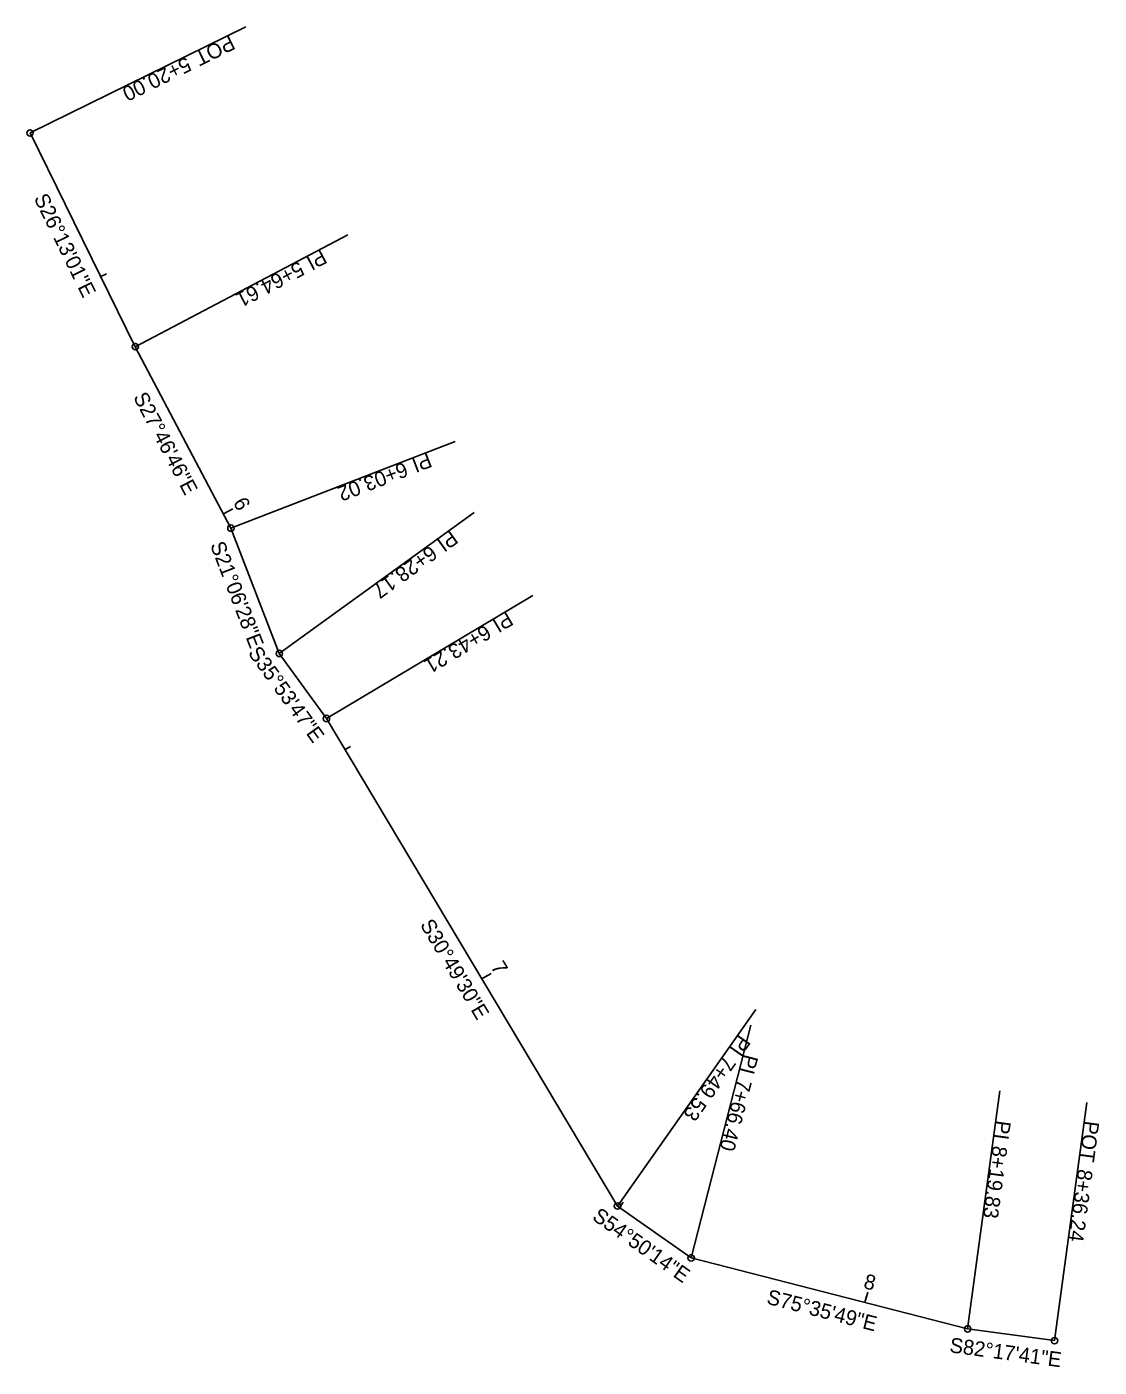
# Model space of a CAD drawing. Extents: x 2352367 to 2352567, y 766880 to 767131.
import ezdxf

# ---------------------------------------------------------------- set-up
doc = ezdxf.new("R2010")
doc.units = 0
for name, color, linetype in [('DR_X_Ditch', 7, 'Continuous'), ('DR_X_Headwall', 7, 'Continuous'), ('GE_P_Alignment', 7, 'Continuous'), ('GE_P_Alignment_100_Stations', 7, 'Continuous'), ('GE_P_Alignment_500_Stations', 7, 'Continuous'), ('RD_X_Fence', 7, 'Continuous'), ('UT_X_Electric', 7, 'Continuous'), ('VG_X_Flower_Bed', 7, 'Continuous'), ('VG_X_Shrub_Line_Lt', 7, 'Continuous')]:
    doc.layers.add(name, color=color, linetype=linetype)

msp = doc.modelspace()

# ---------------------------------------------------------------- linework, layer by layer
at = {"layer": 'DR_X_Ditch'}
for p, q in [((2352367.34, 767110.84), (2352407.71, 767130.72)), ((2352387.05, 767070.82), (2352426.86, 767091.79)), ((2352404.95, 767036.84), (2352446.93, 767053.05)), ((2352414.01, 767013.37), (2352450.46, 767039.75)), ((2352422.83, 767001.19), (2352461.47, 767024.25)), ((2352477.31, 766909.89), (2352503.22, 766946.67)), ((2352491.1, 766900.17), (2352502.29, 766943.76)), ((2352542.85, 766886.88), (2352548.88, 766931.47)), ((2352559.11, 766884.68), (2352565.14, 766929.27))]:
    msp.add_line(p, q, dxfattribs=at)
for centre in [(2352367.34, 767110.84), (2352387.05, 767070.82), (2352404.95, 767036.84), (2352414.01, 767013.37), (2352422.83, 767001.19), (2352477.31, 766909.89), (2352491.1, 766900.17), (2352542.85, 766886.88), (2352559.11, 766884.68)]:
    msp.add_circle(centre, 0.6, dxfattribs=at)
at = {"layer": 'GE_P_Alignment'}
for p, q in [((2352367.34, 767110.84), (2352387.05, 767070.82)), ((2352387.05, 767070.82), (2352404.95, 767036.84)), ((2352404.95, 767036.84), (2352414.01, 767013.37)), ((2352414.01, 767013.37), (2352422.83, 767001.19)), ((2352422.83, 767001.19), (2352477.31, 766909.89)), ((2352477.31, 766909.89), (2352491.1, 766900.17)), ((2352491.1, 766900.17), (2352542.85, 766886.88)), ((2352542.85, 766886.88), (2352559.11, 766884.68))]:
    msp.add_line(p, q, dxfattribs=at)
at = {"layer": 'GE_P_Alignment_100_Stations'}
for p, q in [((2352380.6, 767083.93), (2352381.67, 767084.46)), ((2352403.54, 767039.51), (2352405.31, 767040.44)), ((2352426.31, 766995.36), (2352427.34, 766995.97)), ((2352451.93, 766952.42), (2352453.64, 766953.45)), ((2352477.69, 766909.62), (2352478.38, 766910.6)), ((2352523.64, 766891.81), (2352524.14, 766893.75))]:
    msp.add_line(p, q, dxfattribs=at)
at = {"layer": 'GE_P_Alignment_500_Stations'}
for p, q in [((2352403.54, 767039.51), (2352404.61, 767040.07)), ((2352451.93, 766952.42), (2352452.96, 766953.04)), ((2352523.64, 766891.81), (2352523.94, 766892.98))]:
    msp.add_line(p, q, dxfattribs=at)
at = {"layer": 'RD_X_Fence'}
for p, q in [((2352367.34, 767110.84), (2352407.71, 767130.72)), ((2352387.05, 767070.82), (2352426.86, 767091.79)), ((2352404.95, 767036.84), (2352446.93, 767053.05)), ((2352414.01, 767013.37), (2352450.46, 767039.75)), ((2352422.83, 767001.19), (2352461.47, 767024.25)), ((2352477.31, 766909.89), (2352503.22, 766946.67)), ((2352491.1, 766900.17), (2352502.29, 766943.76)), ((2352542.85, 766886.88), (2352548.88, 766931.47)), ((2352559.11, 766884.68), (2352565.14, 766929.27))]:
    msp.add_line(p, q, dxfattribs=at)
for centre in [(2352367.34, 767110.84), (2352387.05, 767070.82), (2352404.95, 767036.84), (2352414.01, 767013.37), (2352422.83, 767001.19), (2352477.31, 766909.89), (2352491.1, 766900.17), (2352542.85, 766886.88), (2352559.11, 766884.68)]:
    msp.add_circle(centre, 0.6, dxfattribs=at)
at = {"layer": 'VG_X_Flower_Bed'}
for p, q in [((2352367.34, 767110.84), (2352407.71, 767130.72)), ((2352387.05, 767070.82), (2352426.86, 767091.79)), ((2352404.95, 767036.84), (2352446.93, 767053.05)), ((2352414.01, 767013.37), (2352450.46, 767039.75)), ((2352422.83, 767001.19), (2352461.47, 767024.25)), ((2352477.31, 766909.89), (2352503.22, 766946.67)), ((2352491.1, 766900.17), (2352502.29, 766943.76)), ((2352542.85, 766886.88), (2352548.88, 766931.47)), ((2352559.11, 766884.68), (2352565.14, 766929.27))]:
    msp.add_line(p, q, dxfattribs=at)
for centre in [(2352367.34, 767110.84), (2352387.05, 767070.82), (2352404.95, 767036.84), (2352414.01, 767013.37), (2352422.83, 767001.19), (2352477.31, 766909.89), (2352491.1, 766900.17), (2352542.85, 766886.88), (2352559.11, 766884.68)]:
    msp.add_circle(centre, 0.6, dxfattribs=at)

# ---------------------------------------------------------------- texts
at = {"layer": 'DR_X_Ditch'}
for s, rotation, p in [('POT', 206.2169, (2352404.78, 767129.22)), ('5+20.00', 206.2169, (2352396.59, 767125.19)), ('PI', 207.7794, (2352421.9, 767089.12)), ('5+64.61', 207.7794, (2352417.67, 767086.9)), ('PI', 201.1078, (2352441.84, 767051.03)), ('6+03.02', 201.1078, (2352437.38, 767049.31)), ('PI', 215.8964, (2352446.11, 767036.54)), ('6+28.17', 215.8964, (2352442.23, 767033.74)), ('PI', 210.825, (2352456.65, 767021.32)), ('6+43.21', 210.825, (2352452.55, 767018.87)), ('PI', 234.8371, (2352500.1, 766942.16)), ('7+49.53', 234.8371, (2352497.35, 766938.25)), ('PI', 255.597, (2352500.98, 766938.45)), ('7+66.40', 255.597, (2352499.79, 766933.81)), ('PI', 262.2946, (2352548.19, 766926.03)), ('POT', 262.2946, (2352564.74, 766925.96)), ('8+19.83', 262.2946, (2352547.55, 766921.29)), ('8+36.24', 262.2946, (2352563.52, 766916.91))]:
    msp.add_text(s, height=2.8, rotation=rotation, dxfattribs=at).set_placement(p)
at = {"layer": 'DR_X_Headwall'}
for s, rotation, p in [('S26°13\'01"E', 296.2169, (2352368, 767098.64)), ('S27°46\'46"E', 297.7794, (2352386.59, 767061.39)), ('S21°06\'28"E', 291.1078, (2352401.01, 767033.71)), ('S35°53\'47"E', 305.8964, (2352408.04, 767013.43)), ('S30°49\'30"E', 300.825, (2352440.27, 766962.59)), ('S54°50\'14"E', 324.8371, (2352472.39, 766907.48)), ('S75°35\'49"E', 345.597, (2352505.06, 766891.63)), ('S82°17\'41"E', 352.2946, (2352539.36, 766882.51))]:
    msp.add_text(s, height=2.8, rotation=rotation, dxfattribs=at).set_placement(p)
at = {"layer": 'GE_P_Alignment_100_Stations'}
for s, rotation, p in [('6', 297.7794, (2352405.28, 767041.68)), ('7', 300.825, (2352453.48, 766954.7)), ('8', 345.597, (2352523.21, 766894.55))]:
    msp.add_text(s, height=2.8, rotation=rotation, dxfattribs=at).set_placement(p)
at = {"layer": 'RD_X_Fence'}
for s, rotation, p in [('POT', 206.2169, (2352404.78, 767129.22)), ('5+20.00', 206.2169, (2352396.59, 767125.19)), ('PI', 207.7794, (2352421.9, 767089.12)), ('5+64.61', 207.7794, (2352417.67, 767086.9)), ('PI', 201.1078, (2352441.84, 767051.03)), ('6+03.02', 201.1078, (2352437.38, 767049.31)), ('PI', 215.8964, (2352446.11, 767036.54)), ('6+28.17', 215.8964, (2352442.23, 767033.74)), ('PI', 210.825, (2352456.65, 767021.32)), ('6+43.21', 210.825, (2352452.55, 767018.87)), ('PI', 234.8371, (2352500.1, 766942.16)), ('7+49.53', 234.8371, (2352497.35, 766938.25)), ('PI', 255.597, (2352500.98, 766938.45)), ('7+66.40', 255.597, (2352499.79, 766933.81)), ('PI', 262.2946, (2352548.19, 766926.03)), ('POT', 262.2946, (2352564.74, 766925.96)), ('8+19.83', 262.2946, (2352547.55, 766921.29)), ('8+36.24', 262.2946, (2352563.52, 766916.91))]:
    msp.add_text(s, height=2.8, rotation=rotation, dxfattribs=at).set_placement(p)
at = {"layer": 'UT_X_Electric'}
for s, rotation, p in [('S26°13\'01"E', 296.2169, (2352368, 767098.64)), ('S27°46\'46"E', 297.7794, (2352386.59, 767061.39)), ('S21°06\'28"E', 291.1078, (2352401.01, 767033.71)), ('S35°53\'47"E', 305.8964, (2352408.04, 767013.43)), ('S30°49\'30"E', 300.825, (2352440.27, 766962.59)), ('S54°50\'14"E', 324.8371, (2352472.39, 766907.48)), ('S75°35\'49"E', 345.597, (2352505.06, 766891.63)), ('S82°17\'41"E', 352.2946, (2352539.36, 766882.51))]:
    msp.add_text(s, height=2.8, rotation=rotation, dxfattribs=at).set_placement(p)
at = {"layer": 'VG_X_Flower_Bed'}
for s, rotation, p in [('POT', 206.2169, (2352404.78, 767129.22)), ('5+20.00', 206.2169, (2352396.59, 767125.19)), ('PI', 207.7794, (2352421.9, 767089.12)), ('5+64.61', 207.7794, (2352417.67, 767086.9)), ('PI', 201.1078, (2352441.84, 767051.03)), ('6+03.02', 201.1078, (2352437.38, 767049.31)), ('PI', 215.8964, (2352446.11, 767036.54)), ('6+28.17', 215.8964, (2352442.23, 767033.74)), ('PI', 210.825, (2352456.65, 767021.32)), ('6+43.21', 210.825, (2352452.55, 767018.87)), ('PI', 234.8371, (2352500.1, 766942.16)), ('7+49.53', 234.8371, (2352497.35, 766938.25)), ('PI', 255.597, (2352500.98, 766938.45)), ('7+66.40', 255.597, (2352499.79, 766933.81)), ('PI', 262.2946, (2352548.19, 766926.03)), ('POT', 262.2946, (2352564.74, 766925.96)), ('8+19.83', 262.2946, (2352547.55, 766921.29)), ('8+36.24', 262.2946, (2352563.52, 766916.91))]:
    msp.add_text(s, height=2.8, rotation=rotation, dxfattribs=at).set_placement(p)
at = {"layer": 'VG_X_Shrub_Line_Lt'}
for s, rotation, p in [('S26°13\'01"E', 296.2169, (2352368, 767098.64)), ('S27°46\'46"E', 297.7794, (2352386.59, 767061.39)), ('S21°06\'28"E', 291.1078, (2352401.01, 767033.71)), ('S35°53\'47"E', 305.8964, (2352408.04, 767013.43)), ('S30°49\'30"E', 300.825, (2352440.27, 766962.59)), ('S54°50\'14"E', 324.8371, (2352472.39, 766907.48)), ('S75°35\'49"E', 345.597, (2352505.06, 766891.63)), ('S82°17\'41"E', 352.2946, (2352539.36, 766882.51))]:
    msp.add_text(s, height=2.8, rotation=rotation, dxfattribs=at).set_placement(p)

doc.saveas('drawing.dxf')
